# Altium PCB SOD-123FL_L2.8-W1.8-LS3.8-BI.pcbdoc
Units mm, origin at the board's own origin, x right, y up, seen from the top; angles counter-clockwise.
Board outline 17.21 x 14.7 mm, 2 copper layers (Top Layer, Bottom Layer), stack 0 mm thick; 1 components, 0 nets, 2 pads, 0 vias.
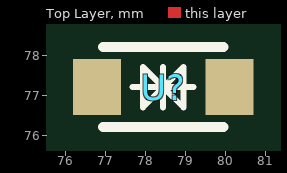
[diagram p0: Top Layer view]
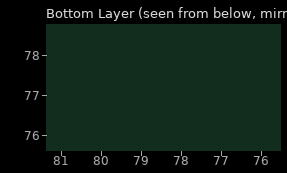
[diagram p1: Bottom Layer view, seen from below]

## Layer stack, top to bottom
Top Layer: signal copper (thickness not stored)
Bottom Layer: signal copper (thickness not stored)

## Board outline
87.061,69.85 69.85,69.85 69.85,84.55 87.061,84.55

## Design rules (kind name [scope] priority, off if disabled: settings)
PasteMaskExpansion "Paste Mask Expansion" [All] p1: expansion=0
SolderMaskExpansion "Solder Mask Expansion" [IsVia] p1: expansion=-25.4 istentingtop=TRUE
SolderMaskExpansion "Solder Mask Expansion" [All] p2: expansion=0.051 istentingtop=FALSE

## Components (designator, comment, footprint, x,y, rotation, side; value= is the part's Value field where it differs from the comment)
U? "" SOD-123FL_L2.8-W1.8-LS3.8-BI 78.456,77.2 r0 top

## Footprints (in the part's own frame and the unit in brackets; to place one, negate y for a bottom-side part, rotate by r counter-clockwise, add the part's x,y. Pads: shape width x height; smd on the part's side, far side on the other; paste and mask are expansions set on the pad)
SOD-123FL_L2.8-W1.8-LS3.8-BI [mm]
  rect 1.2x1.4 smd: 1(-1.656,0) 2(1.656,0)
  silkscreen extent -1.5,-1 1.5,1

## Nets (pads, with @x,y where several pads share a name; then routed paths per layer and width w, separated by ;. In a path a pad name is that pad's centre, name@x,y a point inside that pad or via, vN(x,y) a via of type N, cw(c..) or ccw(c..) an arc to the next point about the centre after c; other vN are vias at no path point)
pads on no net: U?.1 U?.2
